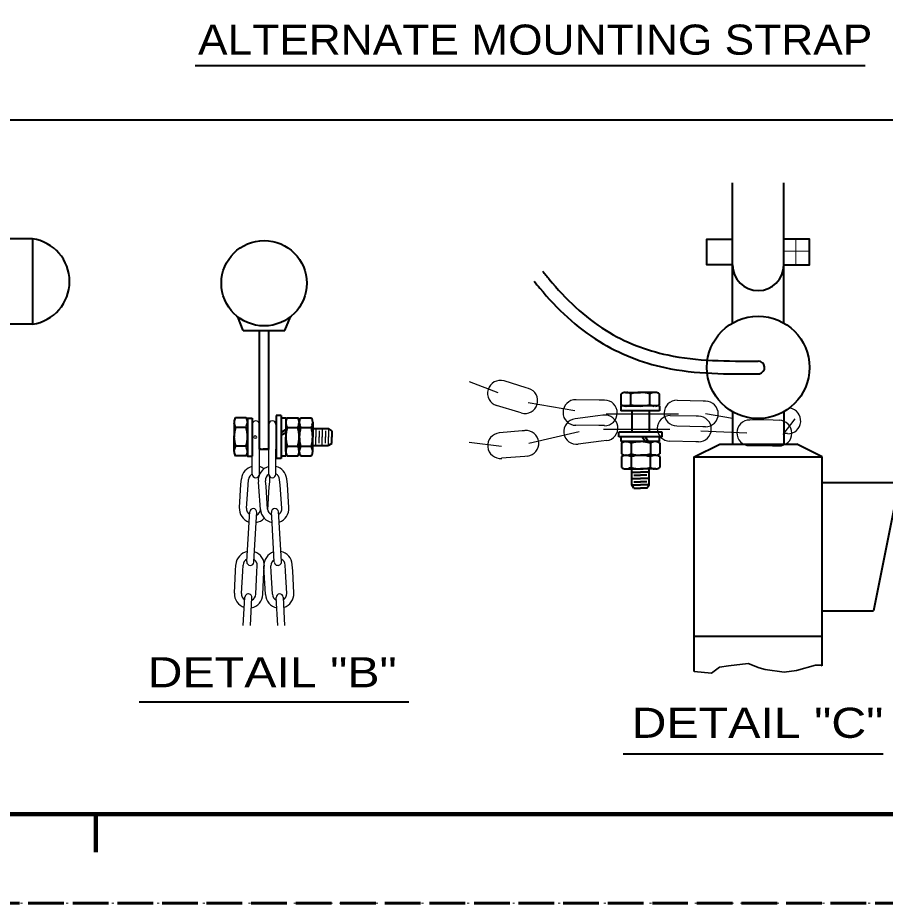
# Model space of a CAD drawing. Extents: x 312583 to 312854, y 144419 to 144597.
# Drawn here: x 312723.42 to 312767.21, y 144418.58 to 144463.32 of the extents above; entities that cross this region are included whole.
import ezdxf

# ---------------------------------------------------------------- set-up
doc = ezdxf.new("R2010")
doc.units = 0
doc.header["$LTSCALE"] = 0.3
doc.header["$PDMODE"] = 32
doc.header["$PDSIZE"] = 0.15
doc.linetypes.add('DOTTED', pattern=[1.5, 0.3, -1.2])
doc.linetypes.add('LONG_DASHED', pattern=[7.5, 6, -1.5])
for name, color, linetype, lineweight in [('1', 7, 'Continuous', 13), ('62', 7, 'DOTTED', 13), ('63', 7, 'LONG_DASHED', 60)]:
    doc.layers.add(name, color=color, linetype=linetype, lineweight=lineweight)

msp = doc.modelspace()

# ---------------------------------------------------------------- linework, layer by layer
at = {"layer": '1', "lineweight": 40}
for p, q in [((312732.3681, 144460.9033), (312766.1986, 144460.9033)), ((312801.9986, 144458.1429), (312616.5, 144458.1429)), ((312759.4982, 144447.9002), (312759.4982, 144454.9842)), ((312762.0895, 144447.9002), (312762.0895, 144454.9842)), ((312724.1625, 144452.1476), (312701.1625, 144452.1476)), ((312724.1625, 144452.1476), (312724.1625, 144447.8389)), ((312724.1625, 144447.8389), (312701.1625, 144447.8389)), ((312734.8038, 144447.5092), (312734.5278, 144448.2069)), ((312736.9045, 144447.5092), (312737.1805, 144448.2069)), ((312734.8038, 144447.5092), (312736.9045, 144447.5092)), ((312735.6165, 144441.5216), (312735.6165, 144447.5092)), ((312753.8785, 144443.7602), (312753.8785, 144444.3199)), ((312754.0932, 144444.3889), (312754.8445, 144444.3889)), ((312754.3692, 144443.7602), (312754.3692, 144444.3199)), ((312755.6035, 144444.3889), (312754.8292, 144444.3889)), ((312755.3275, 144443.7602), (312755.3275, 144444.3276)), ((312755.8105, 144443.7602), (312755.8105, 144444.3199)), ((312736.0918, 144441.5216), (312736.0918, 144443.6529)), ((312755.8105, 144443.4612), (312753.8632, 144443.4612)), ((312754.0855, 144443.7066), (312754.8368, 144443.7066)), ((312754.4152, 144443.4612), (312754.4152, 144442.3879)), ((312755.6035, 144443.7066), (312754.8368, 144443.7066)), ((312755.2892, 144443.4612), (312755.2892, 144442.3879)), ((312755.8105, 144443.7066), (312755.8105, 144443.4612)), ((312759.4982, 144443.4152), (312759.4982, 144441.7746)), ((312762.0895, 144443.4152), (312762.0895, 144441.7746)), ((312734.3362, 144442.8939), (312734.3362, 144442.1349)), ((312734.9495, 144443.1009), (312734.4052, 144443.1009)), ((312735.0185, 144443.0932), (312735.2562, 144443.0932)), ((312735.0185, 144442.8939), (312735.0185, 144442.1349)), ((312735.2562, 144443.0932), (312735.2562, 144441.1766)), ((312736.7052, 144443.2159), (312736.4675, 144443.2159)), ((312736.4675, 144443.2159), (312736.4675, 144441.0539)), ((312736.7052, 144443.2159), (312736.7052, 144441.0539)), ((312736.9428, 144443.0932), (312736.7052, 144443.0932)), ((312736.9428, 144443.0932), (312736.9428, 144441.1766)), ((312736.9428, 144442.8939), (312736.9428, 144442.1349)), ((312737.0118, 144443.1009), (312737.5562, 144443.1009)), ((312737.6252, 144442.8939), (312737.6252, 144442.1349)), ((312737.6252, 144442.8939), (312737.6252, 144442.1349)), ((312737.6865, 144443.1009), (312738.2385, 144443.1009)), ((312738.3075, 144442.8939), (312738.3075, 144442.1349)), ((312734.9495, 144442.6256), (312734.4052, 144442.6256)), ((312736.7052, 144442.3726), (312736.9428, 144442.5182)), ((312737.0118, 144442.6256), (312737.5562, 144442.6256)), ((312737.6942, 144442.6256), (312738.2385, 144442.6256)), ((312738.3075, 144442.5719), (312739.1048, 144442.5719)), ((312739.2658, 144442.4569), (312739.1048, 144442.5719)), ((312739.2658, 144442.4569), (312739.2658, 144442.1349)), ((312734.3362, 144441.3989), (312734.3362, 144442.1426)), ((312735.0185, 144441.3989), (312735.0185, 144442.1349)), ((312736.7052, 144442.2269), (312736.9428, 144442.3726)), ((312736.9428, 144441.3989), (312736.9428, 144442.1349)), ((312737.6252, 144441.3989), (312737.6252, 144442.1426)), ((312737.6252, 144441.3912), (312737.6252, 144442.1349)), ((312738.3075, 144441.3989), (312738.3075, 144442.1349)), ((312739.2658, 144441.8206), (312739.2658, 144442.1426)), ((312753.7558, 144442.1502), (312753.7558, 144442.3879)), ((312755.9408, 144442.3879), (312753.7558, 144442.3879)), ((312755.9408, 144442.1502), (312753.7558, 144442.1502)), ((312753.8785, 144441.9049), (312753.8785, 144442.1502)), ((312754.9442, 144442.1502), (312755.0975, 144441.9049)), ((312755.0898, 144442.1502), (312755.2432, 144441.9049)), ((312755.8182, 144441.9049), (312755.8182, 144442.1502)), ((312755.9408, 144442.1502), (312755.9408, 144442.3879)), ((312734.9495, 144441.6749), (312734.4052, 144441.6749)), ((312737.0118, 144441.6749), (312737.5562, 144441.6749)), ((312737.6865, 144441.6672), (312738.2385, 144441.6672)), ((312738.3075, 144441.7056), (312739.1048, 144441.7056)), ((312739.2658, 144441.8129), (312739.1048, 144441.7056)), ((312755.8182, 144441.9049), (312753.8785, 144441.9049)), ((312753.8938, 144441.8436), (312753.8938, 144441.2839)), ((312754.1008, 144441.9049), (312754.8522, 144441.9049)), ((312754.3768, 144441.8436), (312754.3768, 144441.2839)), ((312755.6188, 144441.9049), (312754.8522, 144441.9049)), ((312755.3505, 144441.8436), (312755.3505, 144441.2762)), ((312755.8335, 144441.8436), (312755.8335, 144441.2839)), ((312764.0292, 144441.1306), (312762.7412, 144441.7746)), ((312734.9495, 144441.1842), (312734.4052, 144441.1842)), ((312736.0918, 144441.5216), (312735.8005, 144441.5216)), ((312736.9428, 144441.1766), (312736.7052, 144441.1766)), ((312737.0118, 144441.1842), (312737.5562, 144441.1842)), ((312737.6865, 144441.1842), (312738.2385, 144441.1842)), ((312753.8862, 144441.1536), (312753.8862, 144440.6016)), ((312754.1008, 144441.2149), (312754.8598, 144441.2149)), ((312754.1008, 144441.2149), (312754.8522, 144441.2149)), ((312754.3768, 144441.1536), (312754.3768, 144440.6016)), ((312755.6188, 144441.2149), (312754.8522, 144441.2149)), ((312755.6188, 144441.2149), (312754.8522, 144441.2149)), ((312755.3428, 144441.1536), (312755.3428, 144440.6016)), ((312755.8258, 144441.1536), (312755.8258, 144440.6016)), ((312757.5585, 144441.1306), (312764.0292, 144441.1306)), ((312764.0292, 144430.5736), (312764.0292, 144441.1306)), ((312736.7052, 144441.0539), (312736.4675, 144441.0539)), ((312754.1008, 144440.5249), (312754.8598, 144440.5249)), ((312754.4152, 144439.7199), (312754.4152, 144440.5249)), ((312754.4152, 144440.3639), (312754.8598, 144440.3639)), ((312754.5225, 144440.2029), (312754.8598, 144440.2029)), ((312755.6188, 144440.5249), (312754.8445, 144440.5249)), ((312755.2892, 144440.3639), (312754.8445, 144440.3639)), ((312755.1742, 144440.2029), (312754.8445, 144440.2029)), ((312755.2892, 144439.7199), (312755.2892, 144440.5249)), ((312754.4152, 144440.0419), (312754.8598, 144440.0419)), ((312754.5225, 144439.8809), (312754.8598, 144439.8809)), ((312755.2892, 144440.0419), (312754.8445, 144440.0419)), ((312755.1742, 144439.8809), (312754.8445, 144439.8809)), ((312754.5225, 144439.5589), (312754.8598, 144439.5589)), ((312755.1742, 144439.5589), (312754.8445, 144439.5589)), ((312764.0292, 144433.3642), (312766.6128, 144433.3642)), ((312757.5585, 144432.0762), (312764.0292, 144432.0762)), ((312729.5445, 144428.7642), (312743.1618, 144428.7642)), ((312753.9842, 144426.1365), (312767.0951, 144426.1365))]:
    msp.add_line(p, q, dxfattribs=at)
at = {"layer": '1'}
for q in [(312762.6952, 144452.1246), (312762.0895, 144451.5266), (312763.3852, 144451.5266), (312762.6952, 144450.8289)]:
    msp.add_line((312762.6952, 144451.5266), q, dxfattribs=at)
at = {"layer": '1', "lineweight": 25}
for p, q in [((312746.2118, 144444.9332), (312747.6532, 144444.3812)), ((312749.1788, 144443.8752), (312751.5325, 144443.4689)), ((312755.4808, 144443.4612), (312754.2158, 144443.4612)), ((312758.1412, 144443.3309), (312759.4905, 144443.0856)), ((312753.1272, 144443.3002), (312756.7688, 144443.3002)), ((312762.0588, 144442.2576), (312762.6568, 144443.0549)), ((312735.2562, 144442.7789), (312735.2562, 144441.5216)), ((312735.6165, 144442.7789), (312735.6165, 144441.5216)), ((312736.0918, 144442.7789), (312736.0918, 144441.5216)), ((312736.4522, 144442.7789), (312736.4522, 144441.5216)), ((312738.4685, 144442.5719), (312738.4685, 144442.1349)), ((312738.6295, 144442.4569), (312738.6295, 144442.1349)), ((312738.7828, 144442.5719), (312738.7828, 144442.1349)), ((312738.9438, 144442.4569), (312738.9438, 144442.1349)), ((312739.1048, 144442.5719), (312739.1048, 144442.1349)), ((312752.9815, 144442.5336), (312756.3318, 144442.5336)), ((312757.8958, 144442.4416), (312760.2265, 144442.3419)), ((312738.4685, 144441.7056), (312738.4685, 144442.1426)), ((312738.6295, 144441.8206), (312738.6295, 144442.1426)), ((312738.7828, 144441.7056), (312738.7828, 144442.1426)), ((312738.9438, 144441.8206), (312738.9438, 144442.1426)), ((312739.1048, 144441.7056), (312739.1048, 144442.1426)), ((312751.7625, 144442.4032), (312749.2172, 144441.8052)), ((312762.2735, 144442.3112), (312762.1048, 144442.3112)), ((312746.2118, 144441.8742), (312747.8372, 144441.6672)), ((312735.2562, 144440.2642), (312735.2562, 144441.5216)), ((312735.6165, 144440.2642), (312735.6165, 144441.5216)), ((312736.0918, 144440.2642), (312736.0918, 144441.5216)), ((312736.4522, 144440.2642), (312736.4522, 144441.5216)), ((312734.8038, 144432.6129), (312734.8805, 144434.0466)), ((312735.1642, 144432.6129), (312735.2408, 144434.0236)), ((312736.5442, 144432.6129), (312736.4675, 144434.0236)), ((312736.9045, 144432.6129), (312736.8278, 144434.0466))]:
    msp.add_line(p, q, dxfattribs=at)
at = {"layer": '1', "lineweight": 158}
msp.add_line((312727.35, 144421.1646), (312727.35, 144423.0846), dxfattribs=at)
msp.add_lwpolyline([(312616.5, 144423.0846), (312849, 144423.0846), (312849, 144585.0846)], dxfattribs=at)
at = {"layer": '1', "lineweight": 40}
for points in [[(312759.4982, 144450.8289), (312758.2025, 144450.8289), (312758.2025, 144452.1246), (312759.4982, 144452.1246)], [(312762.0895, 144450.8289), (312763.3852, 144450.8289), (312763.3852, 144452.1246), (312762.0895, 144452.1246)], [(312735.6165, 144441.5216), (312736.0918, 144441.5216), (312736.0918, 144447.5092)], [(312755.8105, 144443.7066), (312753.8632, 144443.7066), (312753.8632, 144443.4612)], [(312735.0185, 144443.0932), (312735.0185, 144441.1766), (312735.2562, 144441.1766)], [(312735.6932, 144441.5216), (312735.6165, 144441.5216), (312735.6165, 144441.7822)], [(312757.5585, 144430.2976), (312757.5585, 144441.1306), (312758.8542, 144441.7746), (312762.7412, 144441.7746)], [(312764.0292, 144439.8349), (312767.9162, 144439.8349), (312766.6128, 144433.3642)], [(312754.5225, 144439.5589), (312754.4152, 144439.7199), (312754.8598, 144439.7199)], [(312755.1742, 144439.5589), (312755.2892, 144439.7199), (312754.8445, 144439.7199)]]:
    msp.add_lwpolyline(points, dxfattribs=at)
at = {"layer": '1', "lineweight": 25}
for points in [[(312749.2018, 144444.5882), (312749.0792, 144444.6266), (312747.9752, 144444.9716)], [(312753.0352, 144444.0056), (312752.7592, 144444.0056), (312751.6015, 144444.0209)], [(312758.1335, 144443.9442), (312758.0108, 144443.9519), (312756.6998, 144443.9749)], [(312748.8338, 144443.3616), (312748.7112, 144443.3922), (312747.5918, 144443.7296)], [(312752.9585, 144443.2389), (312752.7055, 144443.2006), (312751.5478, 144443.0549)], [(312757.7808, 144443.1852), (312757.6582, 144443.1852), (312756.3548, 144443.2082)], [(312761.8595, 144442.9782), (312761.5528, 144442.9936), (312760.3875, 144443.0089)], [(312749.0025, 144442.4569), (312748.8875, 144442.4416), (312747.7298, 144442.3496)], [(312753.0352, 144442.7176), (312752.7515, 144442.7176), (312751.5785, 144442.7329)], [(312758.1335, 144442.6562), (312758.0032, 144442.6562), (312756.6845, 144442.6869)], [(312753.1578, 144441.9586), (312752.8665, 144441.9202), (312751.7088, 144441.7746)], [(312757.7808, 144441.8896), (312757.6505, 144441.8896), (312756.3242, 144441.9202)], [(312761.8672, 144441.6749), (312761.5145, 144441.6749), (312760.3415, 144441.6979)], [(312749.1405, 144441.1689), (312749.0102, 144441.1536), (312747.8372, 144441.0616)], [(312734.6045, 144438.5699), (312734.6812, 144439.7352), (312734.7118, 144440.0266)], [(312734.9572, 144438.5469), (312735.0415, 144439.7046), (312735.0722, 144439.9882)], [(312735.6702, 144438.4702), (312735.5935, 144439.6126), (312735.5628, 144439.8809)], [(312736.0305, 144438.4932), (312735.9538, 144439.6432), (312735.9232, 144439.9192)], [(312736.0382, 144438.4549), (312736.1148, 144439.6126), (312736.1455, 144439.8809)], [(312736.7512, 144438.5469), (312736.6668, 144439.7046), (312736.6362, 144439.9882)], [(312737.1038, 144438.5699), (312737.0272, 144439.7352), (312736.9965, 144440.0266)], [(312734.9802, 144435.8406), (312735.1105, 144438.1252), (312735.1258, 144438.3552)], [(312735.3405, 144435.8252), (312735.4708, 144438.1022), (312735.4862, 144438.3322)], [(312736.3678, 144435.8252), (312736.2375, 144438.1022), (312736.2222, 144438.3322)], [(312736.7282, 144435.8406), (312736.5978, 144438.1252), (312736.5825, 144438.3552)], [(312734.3515, 144434.2536), (312734.4128, 144435.3806), (312734.4282, 144435.6872)], [(312734.7118, 144434.2306), (312734.7732, 144435.3576), (312734.7885, 144435.6719)], [(312735.4325, 144434.1922), (312735.4862, 144435.3192), (312735.5092, 144435.6336)], [(312735.7852, 144434.1769), (312735.8465, 144435.3039), (312735.8618, 144435.6106)], [(312735.9155, 144434.1769), (312735.8618, 144435.3039), (312735.8388, 144435.6106)], [(312736.2758, 144434.1922), (312736.2145, 144435.3192), (312736.1992, 144435.6336)], [(312736.9965, 144434.2306), (312736.9352, 144435.3576), (312736.9198, 144435.6719)], [(312737.3492, 144434.2536), (312737.2955, 144435.3806), (312737.2725, 144435.6872)]]:
    msp.add_lwpolyline(points, dxfattribs=at)
at = {"layer": '1', "lineweight": 35}
msp.add_lwpolyline([(312757.5585, 144430.2976), (312758.4325, 144430.2056), (312758.8465, 144430.5199), (312759.2912, 144430.5736), (312760.2878, 144430.7039), (312760.8398, 144430.4816), (312761.1465, 144430.3896), (312762.0972, 144430.2516), (312762.7335, 144430.3436), (312763.6842, 144430.6119), (312763.9525, 144430.6119), (312764.0292, 144430.5736)], dxfattribs=at)
at = {"layer": '1', "lineweight": 40}
for centre, radius in [((312735.8522, 144449.9051), 2.1562), ((312760.7943, 144445.6531), 2.5875)]:
    msp.add_circle(centre, radius, dxfattribs=at)
for centre, radius, start, end in [((312723.8539, 144449.9932), 2.1777, 278.04577, 81.95422), ((312760.7943, 144450.8281), 1.2937, 180, 0), ((312760.7943, 144445.6531), 0.3234, 280.70135, 90), ((312754.1015, 144443.991), 0.3996, 91.66257, 124.1297), ((312753.9086, 144443.2714), 1.1442, 66.63635, 78.22986), ((312754.8968, 144442.3272), 2.0649, 91.405, 105.00202), ((312754.7955, 144442.3272), 2.0649, 74.99798, 88.595), ((312755.7838, 144443.2714), 1.1442, 101.77014, 113.36365), ((312755.5908, 144443.991), 0.3996, 55.8703, 88.33743), ((312754.1015, 144444.1011), 0.3996, 235.8703, 268.33743), ((312753.9086, 144444.8207), 1.1442, 281.77014, 293.36365), ((312754.8968, 144445.7648), 2.0649, 254.99798, 268.595), ((312754.7955, 144445.7648), 2.0649, 271.405, 285.00202), ((312755.7838, 144444.8207), 1.1442, 246.63635, 258.22986), ((312755.5908, 144444.1011), 0.3996, 271.66257, 304.1297), ((312734.7281, 144442.8811), 0.3946, 145.8703, 178.33743), ((312734.6194, 144442.8811), 0.3946, 1.66257, 34.1297), ((312737.34, 144442.8811), 0.3946, 145.8703, 178.33743), ((312737.2313, 144442.8811), 0.3946, 1.66257, 34.1297), ((312738.0204, 144442.8792), 0.3946, 145.8703, 178.33743), ((312737.9117, 144442.8792), 0.3946, 1.66257, 34.1297), ((312736.3713, 144442.0956), 2.0394, 164.99798, 178.595), ((312735.4389, 144443.0717), 1.13, 191.77014, 203.36365), ((312733.9087, 144443.0717), 1.13, 336.63635, 348.22986), ((312732.9762, 144442.0956), 2.0394, 1.405, 15.00202), ((312738.0507, 144443.0717), 1.13, 191.77014, 203.36365), ((312738.9832, 144442.0956), 2.0394, 164.99798, 178.595), ((312736.5206, 144443.0717), 1.13, 336.63635, 348.22986), ((312735.5881, 144442.0956), 2.0394, 1.405, 15.00202), ((312738.7311, 144443.0698), 1.13, 191.77014, 203.36365), ((312739.6636, 144442.0937), 2.0394, 164.99798, 178.595), ((312737.201, 144443.0698), 1.13, 336.63635, 348.22986), ((312736.2685, 144442.0937), 2.0394, 1.405, 15.00202), ((312736.3713, 144442.1956), 2.0394, 181.405, 195.00202), ((312732.9762, 144442.1956), 2.0394, 344.99798, 358.595), ((312738.9832, 144442.1956), 2.0394, 181.405, 195.00202), ((312735.5881, 144442.1956), 2.0394, 344.99798, 358.595), ((312739.6636, 144442.1937), 2.0394, 181.405, 195.00202), ((312736.2685, 144442.1937), 2.0394, 344.99798, 358.595), ((312735.4389, 144441.2196), 1.13, 156.63635, 168.22986), ((312733.9087, 144441.2196), 1.13, 11.77014, 23.36365), ((312738.0507, 144441.2196), 1.13, 156.63635, 168.22986), ((312736.5206, 144441.2196), 1.13, 11.77014, 23.36365), ((312738.7311, 144441.2177), 1.13, 156.63635, 168.22986), ((312737.201, 144441.2177), 1.13, 11.77014, 23.36365), ((312754.1151, 144441.5036), 0.3996, 91.66257, 124.1297), ((312753.9221, 144440.784), 1.1442, 66.63635, 78.22986), ((312754.9104, 144439.8399), 2.0649, 91.405, 105.00202), ((312754.8091, 144439.8399), 2.0649, 74.99798, 88.595), ((312755.7974, 144440.784), 1.1442, 101.77014, 113.36365), ((312755.6044, 144441.5036), 0.3996, 55.8703, 88.33743), ((312734.7281, 144441.4102), 0.3946, 181.66257, 214.1297), ((312734.6194, 144441.4102), 0.3946, 325.8703, 358.33743), ((312737.34, 144441.4102), 0.3946, 181.66257, 214.1297), ((312737.2313, 144441.4102), 0.3946, 325.8703, 358.33743), ((312738.0204, 144441.4083), 0.3946, 181.66257, 214.1297), ((312737.9117, 144441.4083), 0.3946, 325.8703, 358.33743), ((312754.1132, 144440.8147), 0.3996, 91.66257, 124.1297), ((312754.1151, 144441.6137), 0.3996, 235.8703, 268.33743), ((312753.9202, 144440.0951), 1.1442, 66.63635, 78.22986), ((312753.9221, 144442.3333), 1.1442, 281.77014, 293.36365), ((312754.9084, 144439.151), 2.0649, 91.405, 105.00202), ((312754.9104, 144443.2775), 2.0649, 254.99798, 268.595), ((312754.8072, 144439.151), 2.0649, 74.99798, 88.595), ((312754.8091, 144443.2775), 2.0649, 271.405, 285.00202), ((312755.7954, 144440.0951), 1.1442, 101.77014, 113.36365), ((312755.7974, 144442.3333), 1.1442, 246.63635, 258.22986), ((312755.6025, 144440.8147), 0.3996, 55.8703, 88.33743), ((312755.6044, 144441.6137), 0.3996, 271.66257, 304.1297), ((312754.1132, 144440.9248), 0.3996, 235.8703, 268.33743), ((312753.9202, 144441.6444), 1.1442, 281.77014, 293.36365), ((312754.9084, 144442.5886), 2.0649, 254.99798, 268.595), ((312754.8072, 144442.5886), 2.0649, 271.405, 285.00202), ((312755.7954, 144441.6444), 1.1442, 246.63635, 258.22986), ((312755.6025, 144440.9248), 0.3996, 271.66257, 304.1297)]:
    msp.add_arc(centre, radius, start, end, dxfattribs=at)
at = {"layer": '1', "lineweight": 25}
for centre, radius, start, end in [((312747.7785, 144444.3473), 0.6469, 73.37363, 253.37362), ((312749.0165, 144443.9715), 0.6469, 253.61189, 73.61189), ((312751.5891, 144443.3754), 0.6469, 89.37363, 269.37362), ((312753.0328, 144443.3554), 0.6469, 269.61189, 89.61189), ((312756.6891, 144443.3444), 0.6469, 89.37363, 269.37362), ((312758.1327, 144443.3036), 0.6469, 269.61189, 89.61189), ((312762.2934, 144442.9517), 0.6469, 269.61189, 80.66149), ((312735.4344, 144442.777), 0.1792, 0, 180), ((312736.2701, 144442.777), 0.1792, 0, 180), ((312751.6298, 144442.4131), 0.6469, 97.37363, 277.37362), ((312753.0611, 144442.594), 0.6469, 277.61189, 97.61189), ((312756.3475, 144442.5707), 0.6469, 89.37363, 269.37362), ((312757.7808, 144442.5403), 0.6469, 269.61189, 89.61189), ((312760.3607, 144442.3482), 0.6469, 89.37363, 269.37362), ((312761.8484, 144442.3333), 0.6469, 269.61189, 89.61189), ((312749.0755, 144441.8141), 0.6469, 275.61189, 95.61189), ((312747.7869, 144441.6988), 0.6469, 95.37363, 275.37362), ((312735.4273, 144439.9542), 0.7188, 103.93517, 174.22394), ((312736.2772, 144439.9542), 0.7188, 104.9421, 185.70589), ((312735.4273, 144439.9542), 0.7188, 53.75949, 75.07528), ((312736.2772, 144439.9542), 0.7188, 5.77606, 76.06483), ((312735.4273, 144439.9542), 0.3594, 118.79308, 174.24956), ((312735.4344, 144440.2623), 0.1792, 180, 0), ((312736.2772, 144439.9542), 0.3594, 121.04328, 185.88348), ((312735.4273, 144439.9542), 0.7188, 352.15115, 24.72299), ((312736.2701, 144440.2623), 0.1792, 180, 0), ((312736.2772, 144439.9542), 0.3594, 5.75044, 61.20692), ((312735.3177, 144438.521), 0.7188, 175.96906, 251.45209), ((312735.3177, 144438.521), 0.3594, 175.96906, 235.88081), ((312735.3051, 144438.3413), 0.1792, 355.96906, 175.96906), ((312735.3177, 144438.521), 0.3594, 295.64054, 349.45786), ((312736.3868, 144438.521), 0.7188, 184.03094, 259.67174), ((312736.3868, 144438.521), 0.3594, 184.03094, 244.29523), ((312736.3994, 144438.3413), 0.1792, 4.03094, 184.03094), ((312736.3868, 144438.521), 0.3594, 304.11919, 4.03094), ((312736.3868, 144438.521), 0.7188, 288.54791, 4.03094), ((312735.3177, 144438.521), 0.7188, 280.28682, 318.04616), ((312735.1474, 144435.6511), 0.7188, 101.22581, 176.70885), ((312735.1474, 144435.6511), 0.7188, 356.70885, 72.34965), ((312736.5571, 144435.6511), 0.7188, 107.65035, 183.29115), ((312736.5571, 144435.6511), 0.7188, 3.29115, 78.77419), ((312735.1474, 144435.6511), 0.3594, 116.7971, 176.70885), ((312735.1577, 144435.831), 0.1792, 176.70885, 356.70885), ((312735.1474, 144435.6511), 0.3594, 356.70885, 56.97314), ((312736.5571, 144435.6511), 0.3594, 123.02686, 183.29115), ((312736.5468, 144435.831), 0.1792, 183.29115, 3.29115), ((312736.5571, 144435.6511), 0.3594, 3.29115, 63.2029), ((312735.0705, 144434.2157), 0.7188, 176.99734, 252.48037), ((312735.0705, 144434.2157), 0.3594, 176.99734, 236.90909), ((312735.0611, 144434.0358), 0.1792, 356.99734, 176.99734), ((312735.0705, 144434.2157), 0.7188, 281.35653, 356.99734), ((312735.0705, 144434.2157), 0.3594, 296.73305, 356.99734), ((312736.634, 144434.2157), 0.7188, 183.00266, 258.64347), ((312736.634, 144434.2157), 0.3594, 183.00266, 243.26695), ((312736.6434, 144434.0358), 0.1792, 3.00266, 183.00266), ((312736.634, 144434.2157), 0.3594, 303.09091, 3.00266), ((312736.634, 144434.2157), 0.7188, 287.51963, 3.00266)]:
    msp.add_arc(centre, radius, start, end, dxfattribs=at)
at = {"layer": '1', "lineweight": 40}
for points in [[(312749.9072, 144450.5222), (312750.2445, 144450.1082), (312753.1118, 144447.5169), (312756.2245, 144446.2826), (312760.7938, 144445.9759)], [(312749.4855, 144450.0086), (312749.7692, 144449.6559), (312752.7745, 144446.9649), (312756.0788, 144445.6462), (312760.8552, 144445.3242)]]:
    msp.add_spline(points, degree=3, dxfattribs=at)
at = {"layer": '1'}
msp.add_point((312735.4095, 144442.1349), dxfattribs=at)
at = {"layer": '62'}
msp.add_lwpolyline([(312601.2, 144418.5846), (312853.5, 144418.5846), (312853.5, 144596.7846)], dxfattribs=at)
at = {"layer": '63'}
msp.add_line((312851.75, 144418.5846), (312583.526, 144418.5846), dxfattribs=at)

# ---------------------------------------------------------------- texts
at = {"layer": '1'}
for s, width, p in [('ALTERNATE MOUNTING STRAP', 1.1, (312732.5159, 144461.4497)), ('DETAIL "B"', 1.2, (312729.971, 144429.4946)), ('DETAIL "C"', 1.2, (312754.4014, 144426.9417))]:
    msp.add_text(s, height=1.52, dxfattribs=dict(at, width=width)).set_placement(p)

doc.saveas('drawing.dxf')
